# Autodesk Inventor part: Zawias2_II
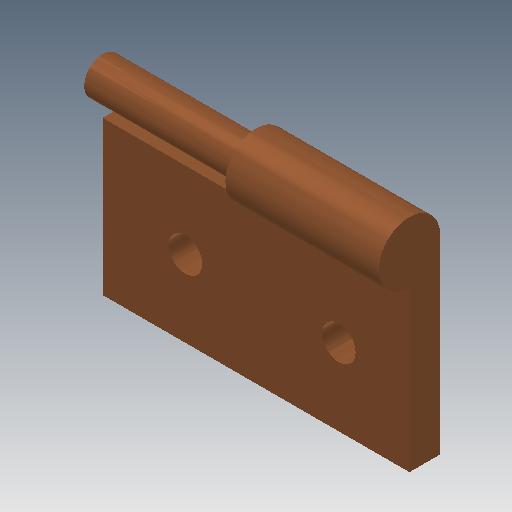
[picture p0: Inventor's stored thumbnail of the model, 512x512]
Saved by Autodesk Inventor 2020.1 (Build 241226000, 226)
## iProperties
Created: 2005-09
Part Number: Zawias2_II
Document SubType Name: Modeling
Designer: F.Stasiak
Density: 1 g/cm^3
Mass: 8.92117 g
Surface Area: 46.2756 cm^2
Volume: 8.92117 cm^3
Material: Ogólny
Appearance: Miedziany (stary/polerowany)
Manager: www.cadconsulting.pl
Company: Fabian Stasiak CAD Consulting
d0: 50,000 mm
d2: 23,000 mm
d4: 5,000 mm
d5: 0,00 deg
d7: 0,00 deg
d9: 6,000 mm
d10: 25,000 mm
d11: 0,00 deg
d12: 5,500 mm
d20: 25,000 mm
d21: 6,000 mm
d22: 10,000 mm
Author: F.Stasiak
Subject: Zbiór ćwiczeń. Autodesk Inventor 2020. Kurs podstawowy
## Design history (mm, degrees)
sketch "Szkic1"
  geometry: L1 (2, 31)-(25, 31); L2 (25, 31)-(25, 0); L3 (25, 0)-(-25, 0); L4 (-25, 0)-(-25, 25); L5 (-25, 25)-(2, 25); L6 (2, 25)-(2, 31); 2 further points
  constraints: 12 end point, 3 parallel, 2 perpendicular, 1 coincident, 1 horizontal, 1 midpoint
  dimensions: "d0" = 50 distance of L2.end L3.end; "d2" = 23 distance of L1.start L1.end (computed from d0); "d20" = 25 distance of L3.end L4.end; "d21" = 6 distance of L5.end L1.start
extrude "Wyciągnięcie proste1" new body sketch "Szkic1" distance "d4" = 5; taper "d5" = 0 deg
sketch "Szkic2"
  geometry: L1 (5, 0)-(5, 6) reference; L2 (0, 0)-(0, 6) reference; C1 r 5 at (5, 6)
  constraints: 1 centre point, 1 coincident
  dimensions: "d22" = 10 diameter of C1
extrude "Wyciągnięcie proste2" join sketch "Szkic2" stored distance "d6" = 10; taper "d7" = 0 deg
sketch "Szkic3"
  geometry: C1 r 5 at (0, 0) reference; C2 r 3 at (0, 0)
  constraints: 1 centre point, 1 coincident
  dimensions: "d9" = 6 diameter of C2
extrude "Wyciągnięcie proste3" cut sketch "Szkic3" distance "d10" = 25; taper "d11" = 0 deg
sketch "Szkic4"
  geometry: L1 (-25, 0)-(-25, 25) reference; L2 (25, 26)-(25, 0) reference; L3 (25, 26)-(2, 26) reference; L4 (-25, 25)-(2, 25) reference; L5 (-25, 12.5)-(25, 12.5); L6 (-11.5, 25)-(-11.5, 12.5); L7 (13.5, 26)-(13.5, 12.5)
  constraints: 6 end point, 3 midpoint, 3 perpendicular, 3 point on line
hole "Otwór1" sketch "Szkic4" at (-11.5, 12.5), (13.5, 12.5) diameter "d12" = 5.5; stored, may be unused: countersink angle "d16" = 90 deg, drill point angle "d18" = 118 deg; dims "d13" = 6, "d14" = 4, "d15" = 2, "d17" = 8
node "Bryła1"
node "Korpusy bryłowe"
node "Korpusy powierzchniowe"
node "Pętla rzutowana1"
